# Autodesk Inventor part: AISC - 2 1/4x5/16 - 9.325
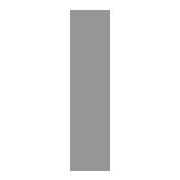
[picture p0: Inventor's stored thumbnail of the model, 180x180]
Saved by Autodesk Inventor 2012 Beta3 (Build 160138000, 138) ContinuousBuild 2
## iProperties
IsCustomPart: 1
Created: 2010-11
Part Number: AISC - 2 1/4x5/16 - 9.325
Material: Steel, Mild
Description: Flat Bar Steel
Document SubType Name: Modeling
Standard: ANSI
Designer: Beta-8540w
Standards Organization: ANSI
Language: en-US
Size Designation: 2 1/4x5/16
Categories: <MemberInstance><Categories><Category DisplayName="Structural Shapes" InternalName="089c4875-fa83-4c05-b084-43b9cc11f5ed" Mnemonic="GRDR"><CategoryParameter Dis
Stock Number: 2 1/4x5/16
Density: 7.86 g/cm^3
_CCFamilyMember: 149
_CCFamilyDisplayName: ANSI AISC (Rectangular) - Flat Bar Steel
_FrameMemberDoc: Frame Member File
_Version: 15.0.0
_GetPNFromCC: 1
G_L: 9.325 in
G_W: 0.313 in
G_H: 2.250 in
Author: Beta-8540w
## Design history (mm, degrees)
node "Start plane"
node "End plane"
node "Driven Length"
  sketch "Sketch3"
    geometry: L1 (0, 0)-(10, 0) reference
    constraints: 2 end point, 1 horizontal
  workplane "Work Plane3"
  sketch "Sketch4"
    geometry: L1 (-2, 0)-(12, 0) reference; L2 (-40.005, 236.864)-(40.005, 236.864) reference
    dimensions: "d9" = 236.86413 distance between parallel lines of L1 L2 (derived)
sketch "Sweep Path"
  geometry: L1 through (25.4, 40.279) direction (-1, 0); L2 through (112.121, 127) direction (-1, 0); 9 other entities
  constraints: 10 horizontal
node "Orientation Work Plane"
feature "Body" dims "d10" = 0
body "Solid1"
sketch "Sketch"
  geometry: L1 (3.969, -28.575)-(-3.969, -28.575); L2 (-3.969, -28.575)-(-3.969, 28.575); L3 (-3.969, 28.575)-(3.969, 28.575); L4 (3.969, 28.575)-(3.969, -28.575); L5 (-6, 0)-(8, 0); L6 (0, -30)-(0, 40); L7 (0, 54)-(0, -44); L8 (-9.2, 0)-(13.2, 0)
  constraints: 16 end point, 2 collinear, 2 parallel, 1 horizontal, 1 perpendicular
  dimensions: "d0" = 57.15 distance between parallel lines of L3 L1 (= G_W); "d1" = 7.9375 distance between parallel lines of L4 L2 (= G_H); "d4" = 3.96875 distance between parallel lines of L6 L4 (= 0.5 x d1); "d5" = 28.575 distance between parallel lines of L5 L3 (= 0.5 x d0)
other parameters: "G_W" = 57.15 [user parameter; used in 1 equation term], "G_H" = 7.9375 [user parameter; used in 1 equation term], "G_L" = 236.86413 (= d9) [user parameter], "G_OFFSET_START" = 0 [user parameter; used in 1 equation term], "G_OFFSET_END" = 0 [user parameter; used in 1 equation term], "d6" = 0 (computed from G_OFFSET_START), "d7" = 236.86413 (= G_OFFSET_END + B_L), "B_L" = 236.86413 [user parameter; used in 1 equation term], "d8" = 90 deg
